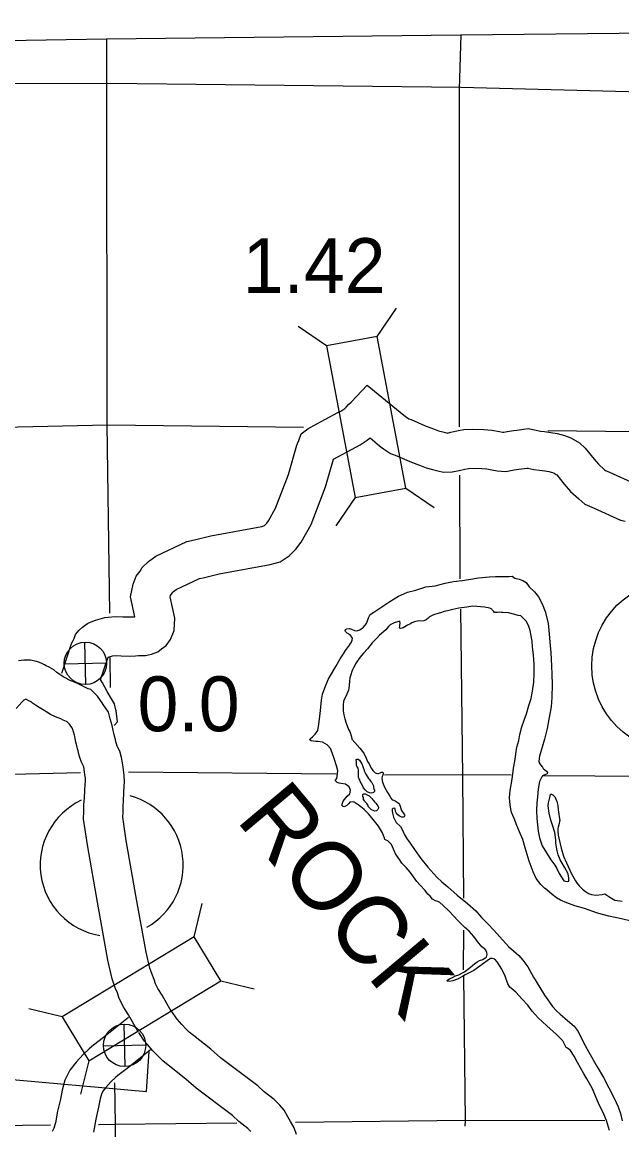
# Model space of a CAD drawing. Extents: x 77230 to 630905, y 790554 to 1662844.
# Drawn here: x 342524 to 351748, y 1622566 to 1639610 of the extents above; entities that cross this region are included whole.
import ezdxf

# ---------------------------------------------------------------- set-up
doc = ezdxf.new("R2010")
doc.units = 0
for name, color, linetype in [('Level 14', 7, 'Continuous'), ('Level 16', 7, 'Continuous'), ('Level 17', 7, 'Continuous'), ('Level 19', 7, 'Continuous'), ('Level 22', 7, 'Continuous'), ('Level 23', 7, 'Continuous'), ('Level 26', 7, 'Continuous'), ('Level 31', 7, 'Continuous'), ('Level 32', 7, 'Continuous'), ('Level 33', 7, 'Continuous'), ('Level 34', 7, 'Continuous')]:
    doc.layers.add(name, color=color, linetype=linetype)

msp = doc.modelspace()

# ---------------------------------------------------------------- linework, layer by layer
at = {"layer": 'Level 14'}
msp.add_lwpolyline([(338556, 1639267), (343823, 1639351), (349273, 1639417), (354630, 1639473), (359059, 1639529), (364378, 1639584), (367437, 1639610)], dxfattribs=at)
at = {"layer": 'Level 16'}
for points in [[(343823, 1639351), (343819, 1638672), (343825, 1633418), (343865, 1630514)], [(349273, 1639417), (349244, 1638581), (349246, 1633383)], [(354631, 1638464), (349271, 1638604), (343841, 1638666), (338567, 1638659), (333182, 1638541)], [(346851, 1633371), (343835, 1633410), (338542, 1633291), (336598, 1633267)], [(354599, 1633274), (350612, 1633323)], [(349249, 1632641), (349255, 1631046)], [(349264, 1630580), (349295, 1628000), (349311, 1626130)], [(343874, 1629832), (343880, 1629370)], [(343419, 1628061), (338580, 1627939), (333319, 1627911)], [(347353, 1628041), (344162, 1628071)], [(350045, 1628023), (349285, 1628028), (348095, 1628025)], [(354575, 1627989), (350525, 1628014)], [(349312, 1625639), (349308, 1625030)], [(349315, 1624934), (349336, 1622709), (349335, 1622623)], [(343946, 1623291), (343953, 1622646), (343954, 1621548)], [(342958, 1622636), (338648, 1622586), (333384, 1622611)], [(345827, 1622668), (343947, 1622648), (343700, 1622645)], [(351487, 1622703), (349340, 1622707), (346730, 1622678)]]:
    msp.add_lwpolyline(points, dxfattribs=at)
at = {"layer": 'Level 17'}
for points in [[(347460, 1627539), (347440, 1627559), (347464, 1627623), (347523, 1627700), (347566, 1627738), (347574, 1627794), (347553, 1627842), (347497, 1627883), (347433, 1627893), (347399, 1627899), (347367, 1627912), (347339, 1627942), (347364, 1627974), (347381, 1628089), (347360, 1628168), (347323, 1628282), (347292, 1628368), (347266, 1628434), (347215, 1628491), (347145, 1628533), (347077, 1628540), (347043, 1628542), (347003, 1628545), (346969, 1628553), (346948, 1628569), (346952, 1628583), (346990, 1628611), (347030, 1628652), (347073, 1628710), (347086, 1628807), (347109, 1628967), (347129, 1629177), (347146, 1629272), (347181, 1629368), (347233, 1629497), (347267, 1629559), (347350, 1629694), (347416, 1629813), (347466, 1629890), (347495, 1629940), (347529, 1629984), (347558, 1630025), (347574, 1630047), (347590, 1630071), (347602, 1630101), (347603, 1630133), (347567, 1630183), (347525, 1630207), (347496, 1630236), (347490, 1630250), (347498, 1630262), (347518, 1630273), (347558, 1630279), (347590, 1630269), (347638, 1630250), (347672, 1630246), (347720, 1630259), (347776, 1630303), (347821, 1630356), (347833, 1630380), (347850, 1630444), (347878, 1630495), (347931, 1630533), (348088, 1630633), (348178, 1630696), (348315, 1630777), (348452, 1630839), (348580, 1630868), (348734, 1630920), (348879, 1630937), (349029, 1630979), (349161, 1631002), (349294, 1631021), (349396, 1631036), (349542, 1631058), (349706, 1631073), (349806, 1631078), (349928, 1631078), (350012, 1631080), (350060, 1631083), (350104, 1631057), (350170, 1631040), (350224, 1631018), (350279, 1630989), (350323, 1630919), (350404, 1630846), (350465, 1630767), (350524, 1630659), (350567, 1630543), (350617, 1630364), (350630, 1630193), (350641, 1630075), (350655, 1629903), (350667, 1629703), (350670, 1629571), (350676, 1629425), (350672, 1629219), (350661, 1629074), (350627, 1628886), (350602, 1628741), (350560, 1628579)], [(350393, 1629456), (350400, 1629590), (350399, 1629725), (350387, 1629873), (350374, 1629991), (350367, 1630085), (350338, 1630251), (350311, 1630328), (350276, 1630392), (350194, 1630477), (350154, 1630481), (350103, 1630495), (350005, 1630522), (349917, 1630525), (349893, 1630527), (349859, 1630530), (349837, 1630524), (349791, 1630528), (349777, 1630541), (349755, 1630565), (349749, 1630575), (349717, 1630591), (349638, 1630610), (349458, 1630622), (349362, 1630609), (349323, 1630603), (349243, 1630592), (349151, 1630573), (349069, 1630552), (349015, 1630540), (348957, 1630521), (348900, 1630505), (348868, 1630494), (348832, 1630482), (348800, 1630464), (348792, 1630460), (348776, 1630445), (348766, 1630433), (348736, 1630413), (348701, 1630399), (348645, 1630394), (348623, 1630398), (348561, 1630381), (348517, 1630365), (348487, 1630348), (348453, 1630330), (348410, 1630306), (348384, 1630291), (348368, 1630285), (348346, 1630279), (348334, 1630281), (348328, 1630297), (348331, 1630315), (348333, 1630329), (348339, 1630355), (348331, 1630393), (348247, 1630366), (348187, 1630335), (348161, 1630311), (348116, 1630261), (348023, 1630176), (347979, 1630129), (347908, 1630060), (347835, 1629969), (347774, 1629899), (347718, 1629836), (347661, 1629751), (347618, 1629677), (347602, 1629635), (347575, 1629552), (347565, 1629520), (347560, 1629470), (347554, 1629404), (347551, 1629364), (347545, 1629332), (347529, 1629296), (347506, 1629245), (347476, 1629185), (347467, 1629155), (347461, 1629103), (347460, 1629047), (347464, 1629011), (347473, 1628951), (347485, 1628889), (347510, 1628825), (347543, 1628727), (347563, 1628693), (347590, 1628613), (347596, 1628579), (347643, 1628528), (347720, 1628438), (347760, 1628389), (347783, 1628349), (347817, 1628287), (347836, 1628235), (347860, 1628195), (347876, 1628160), (347895, 1628128), (347917, 1628096), (347955, 1628058), (347969, 1628052)], [(351893, 1625777), (351741, 1625813), (351548, 1625853), (351376, 1625902), (351173, 1625970), (351023, 1626012), (350900, 1626061), (350806, 1626102), (350744, 1626138), (350675, 1626185), (350592, 1626258), (350560, 1626286), (350500, 1626339), (350431, 1626431), (350382, 1626538), (350324, 1626700), (350262, 1626906), (350223, 1627034), (350176, 1627153), (350133, 1627251), (350090, 1627355), (350053, 1627450), (350042, 1627498), (350030, 1627566), (350021, 1627674), (350030, 1627787), (350054, 1627929), (350069, 1628039), (350084, 1628129), (350105, 1628262), (350116, 1628350), (350135, 1628452), (350164, 1628559), (350179, 1628647), (350210, 1628768), (350245, 1628868), (350280, 1628966), (350319, 1629095), (350352, 1629203), (350375, 1629314), (350393, 1629456)], [(350560, 1628579), (350506, 1628402), (350481, 1628314), (350473, 1628239), (350478, 1628211), (350498, 1628184), (350526, 1628144), (350540, 1628126), (350563, 1628104), (350589, 1628084), (350603, 1628063), (350597, 1628042), (350537, 1628020), (350516, 1627998), (350482, 1627927), (350463, 1627809), (350449, 1627691), (350443, 1627598), (350437, 1627478), (350440, 1627356), (350462, 1627164), (350483, 1627058), (350524, 1626936), (350591, 1626827), (350658, 1626721), (350717, 1626638), (350749, 1626586), (350786, 1626510), (350819, 1626453), (350855, 1626397), (350883, 1626393), (350909, 1626386), (350931, 1626392), (350935, 1626440), (350920, 1626506), (350865, 1626609), (350828, 1626671), (350802, 1626721), (350769, 1626799), (350755, 1626859), (350744, 1626913), (350733, 1626977), (350731, 1627021), (350729, 1627071), (350716, 1627141), (350683, 1627252), (350656, 1627332), (350629, 1627440), (350614, 1627550), (350621, 1627598), (350639, 1627682), (350650, 1627727), (350652, 1627729), (350668, 1627733), (350688, 1627721), (350717, 1627689), (350735, 1627653), (350747, 1627619), (350762, 1627558), (350770, 1627492), (350781, 1627424), (350786, 1627380), (350792, 1627328), (350790, 1627309), (350783, 1627277), (350767, 1627221), (350763, 1627203), (350762, 1627157), (350768, 1627099), (350779, 1627053), (350798, 1626965), (350814, 1626899), (350851, 1626775), (350896, 1626674), (350976, 1626506), (351033, 1626399), (351051, 1626369), (351094, 1626321), (351144, 1626270), (351187, 1626232), (351233, 1626201), (351279, 1626187), (351349, 1626176), (351443, 1626189), (351487, 1626197), (351561, 1626148), (351638, 1626100), (351754, 1626086)], [(347766, 1627856), (347725, 1627924), (347716, 1627950), (347706, 1627967), (347700, 1627987), (347698, 1627997), (347698, 1628015), (347699, 1628033), (347699, 1628053), (347699, 1628069), (347695, 1628091), (347696, 1628099), (347692, 1628129), (347674, 1628163), (347669, 1628179), (347667, 1628205), (347665, 1628217), (347665, 1628239), (347664, 1628247), (347662, 1628257), (347664, 1628263), (347678, 1628267), (347690, 1628268), (347712, 1628254), (347727, 1628230), (347747, 1628198), (347766, 1628159), (347774, 1628127), (347778, 1628117), (347791, 1628077), (347809, 1628037)], [(347809, 1628037), (347850, 1627973), (347866, 1627956), (347885, 1627926), (347901, 1627908), (347926, 1627860), (347930, 1627834), (347934, 1627808), (347943, 1627793), (347941, 1627772), (347929, 1627758), (347919, 1627752), (347891, 1627748), (347867, 1627749), (347829, 1627765), (347801, 1627797), (347776, 1627828), (347766, 1627856)], [(347969, 1628052), (347991, 1628051), (348005, 1628051), (348031, 1628059), (348053, 1628067), (348065, 1628071), (348081, 1628052), (348079, 1628045), (348077, 1628039), (348072, 1628023), (348064, 1628001), (348056, 1627971), (348065, 1627917), (348095, 1627841), (348146, 1627758), (348181, 1627698), (348201, 1627664), (348213, 1627646), (348219, 1627644), (348239, 1627639), (348263, 1627629), (348292, 1627609), (348314, 1627593), (348328, 1627573), (348340, 1627545), (348349, 1627511), (348359, 1627480), (348369, 1627464), (348383, 1627444), (348395, 1627430), (348407, 1627414), (348408, 1627402), (348400, 1627382), (348382, 1627378), (348364, 1627379), (348338, 1627387), (348324, 1627397), (348301, 1627415), (348279, 1627445), (348269, 1627465), (348261, 1627507), (348255, 1627517), (348225, 1627508), (348215, 1627498), (348215, 1627476), (348219, 1627436), (348234, 1627376), (348277, 1627295), (348343, 1627233), (348382, 1627157), (348398, 1627113), (348447, 1627038), (348484, 1626990), (348567, 1626865), (348654, 1626740), (348765, 1626607), (348901, 1626452), (348979, 1626382), (349070, 1626305), (349213, 1626178), (349375, 1626046), (349500, 1625935), (349591, 1625834), (349698, 1625725), (349776, 1625645), (349874, 1625534), (350007, 1625385), (350082, 1625318), (350122, 1625284), (350164, 1625249), (350223, 1625179), (350302, 1625072), (350387, 1624917), (350485, 1624755), (350560, 1624640), (350611, 1624566), (350682, 1624465), (350742, 1624397), (350801, 1624346), (350873, 1624285), (350946, 1624219), (351013, 1624162), (351075, 1624080), (351159, 1623911), (351238, 1623762), (351371, 1623537), (351464, 1623369), (351550, 1623210), (351631, 1623051), (351693, 1622921), (351726, 1622819), (351753, 1622703)], [(351294, 1623207), (351208, 1623353), (351156, 1623440), (351068, 1623602), (351015, 1623699), (350956, 1623789), (350914, 1623820), (350890, 1623832), (350874, 1623862), (350841, 1623936), (350742, 1624035), (350595, 1624164), (350463, 1624288), (350368, 1624392), (350300, 1624485), (350215, 1624574), (350116, 1624682), (350027, 1624761), (349992, 1624812), (349951, 1624928), (349904, 1625040), (349829, 1625153), (349793, 1625191), (349755, 1625201), (349727, 1625200), (349679, 1625168), (349621, 1625127), (349562, 1625083), (349469, 1625016), (349401, 1624983), (349337, 1624950), (349299, 1624926), (349220, 1624885), (349150, 1624856), (349092, 1624846), (349064, 1624851), (349056, 1624863), (349098, 1624888), (349142, 1624908), (349187, 1624933), (349241, 1624953), (349285, 1624974), (349327, 1624998), (349374, 1625033), (349418, 1625067), (349454, 1625099), (349482, 1625122), (349525, 1625150), (349561, 1625169), (349609, 1625185), (349647, 1625210), (349665, 1625224), (349676, 1625264), (349674, 1625292), (349658, 1625330), (349637, 1625354), (349617, 1625365), (349597, 1625383), (349579, 1625401), (349542, 1625443), (349473, 1625540), (349399, 1625622), (349334, 1625677), (349231, 1625782), (349090, 1625933), (348999, 1626018), (348951, 1626062), (348916, 1626081), (348884, 1626089), (348838, 1626115), (348800, 1626160), (348765, 1626192), (348721, 1626246), (348648, 1626333), (348597, 1626389), (348492, 1626528), (348431, 1626601), (348389, 1626641), (348363, 1626671), (348330, 1626728), (348269, 1626812), (348235, 1626882), (348204, 1626957), (348149, 1627015), (348121, 1627023), (348105, 1627032), (348097, 1627054), (348068, 1627134), (348003, 1627236), (347900, 1627369), (347851, 1627426), (347785, 1627496), (347734, 1627537), (347692, 1627567), (347630, 1627608), (347602, 1627614), (347564, 1627608), (347548, 1627588), (347516, 1627557), (347478, 1627535), (347460, 1627539)], [(347773, 1627648), (347772, 1627680), (347766, 1627694), (347766, 1627722), (347766, 1627724), (347771, 1627732), (347779, 1627734), (347799, 1627734), (347822, 1627725), (347864, 1627703), (347900, 1627662), (347919, 1627642), (347935, 1627626), (347945, 1627614), (347965, 1627593), (347994, 1627553)], [(347994, 1627553), (348006, 1627527), (348004, 1627513), (347993, 1627493), (347985, 1627483), (347973, 1627476), (347949, 1627470), (347899, 1627491), (347887, 1627501), (347848, 1627543), (347844, 1627555), (347827, 1627585), (347801, 1627612), (347797, 1627622), (347773, 1627648)], [(351558, 1622555), (351511, 1622709), (351470, 1622809), (351390, 1622978), (351294, 1623207)]]:
    msp.add_lwpolyline(points, dxfattribs=at)
at = {"layer": 'Level 19'}
for p, q in [((347983, 1634775), (348281, 1635211)), ((347205, 1634629), (346769, 1634927)), ((348423, 1632440), (348859, 1632143)), ((347645, 1632294), (347347, 1631858)), ((345169, 1625536), (345294, 1626049)), ((345580, 1624859), (346093, 1624734)), ((343138, 1624304), (342625, 1624429)), ((343549, 1623627), (343423, 1623114))]:
    msp.add_line(p, q, dxfattribs=at)
for points in [[(348423, 1632440), (347983, 1634775), (347205, 1634629), (347645, 1632294)], [(345169, 1625536), (343138, 1624304), (343549, 1623627), (345580, 1624859)]]:
    msp.add_lwpolyline(points, close=True, dxfattribs=at)
at = {"layer": 'Level 22'}
for points in [[(343132, 1629593), (343284, 1630048), (343306, 1630094), (343322, 1630127), (343346, 1630190), (343399, 1630255), (343450, 1630303), (343491, 1630333), (343530, 1630358), (343586, 1630384), (343654, 1630407), (343797, 1630447), (343954, 1630466), (344074, 1630460), (344178, 1630457), (344225, 1630459), (344255, 1630461), (344188, 1630766), (344209, 1630865), (344229, 1630961), (344277, 1631087), (344338, 1631164), (344372, 1631221), (344468, 1631309), (344579, 1631393), (345056, 1631620), (345176, 1631646), (345427, 1631706), (346210, 1631851), (346239, 1631859), (346250, 1631866), (346287, 1631902), (346313, 1631936), (346422, 1632134), (346619, 1632651), (346751, 1633099), (346756, 1633113), (346761, 1633129), (346778, 1633174), (346816, 1633274), (346920, 1633354), (346966, 1633378), (346999, 1633397), (347381, 1633606), (347424, 1633626), (347485, 1633667), (347498, 1633677), (347505, 1633683), (347510, 1633687), (347544, 1633728), (347586, 1633764), (347832, 1634026), (348394, 1633565), (348438, 1633531), (348471, 1633508), (348509, 1633494), (348713, 1633406), (348852, 1633354), (348927, 1633324), (348993, 1633306), (349055, 1633289), (349061, 1633288), (349069, 1633288), (349116, 1633299), (349208, 1633319), (349316, 1633341), (349456, 1633348), (349627, 1633342), (349750, 1633334), (349867, 1633311), (349912, 1633302), (349933, 1633301), (349986, 1633310), (350080, 1633327), (350132, 1633332), (350306, 1633359), (350430, 1633332)], [(343937, 1628786), (343992, 1628842), (343968, 1629011), (343960, 1629051), (343942, 1629119), (343899, 1629199), (343829, 1629313), (343758, 1629442), (343734, 1629487), (343732, 1629491), (343731, 1629494), (343841, 1629822), (343847, 1629833), (343849, 1629839), (343915, 1629857), (343977, 1629864), (344049, 1629861), (344181, 1629856), (344266, 1629860), (344313, 1629864), (344352, 1629865), (344420, 1629866), (344514, 1629883), (344609, 1629923), (344668, 1629965), (344741, 1630019), (344808, 1630110), (344864, 1630248), (344873, 1630440), (344802, 1630769), (344805, 1630788), (344833, 1630823), (344843, 1630839), (344853, 1630848), (344893, 1630878), (345250, 1631048), (345309, 1631061), (345552, 1631119), (346341, 1631265), (346491, 1631304), (346631, 1631400), (346736, 1631502), (346816, 1631606), (346968, 1631880), (347188, 1632459), (347313, 1632885), (347656, 1633072), (347724, 1633105), (347833, 1633178), (347864, 1633202), (347878, 1633212), (348023, 1633092), (348084, 1633047), (348188, 1632973), (348287, 1632936), (348489, 1632850), (348636, 1632794), (348737, 1632754), (348836, 1632727), (348919, 1632705), (349005, 1632687), (349140, 1632689), (349245, 1632713), (349332, 1632732), (349392, 1632744), (349460, 1632748), (349596, 1632743), (349673, 1632737), (349749, 1632723), (349832, 1632706), (349964, 1632697), (350090, 1632719), (350163, 1632732), (350207, 1632736), (350289, 1632749), (350305, 1632746)], [(350431, 1633332), (350495, 1633318), (350560, 1633311), (350658, 1633297), (350752, 1633281), (350865, 1633251), (350965, 1633214), (351097, 1633137), (351186, 1633054), (351322, 1632886), (351388, 1632809), (351484, 1632721), (351496, 1632711), (351560, 1632685), (351942, 1632512)], [(350304, 1632746), (350396, 1632726), (350483, 1632716), (350566, 1632704), (350625, 1632694), (350684, 1632678), (350708, 1632669), (350737, 1632652), (350746, 1632644), (350862, 1632500), (350958, 1632390), (351085, 1632273), (351179, 1632193), (351323, 1632134), (351730, 1631949), (351798, 1631929)], [(344161, 1624296), (343774, 1623985), (343620, 1623871), (343553, 1623812), (343460, 1623723), (343356, 1623609), (343255, 1623483), (343179, 1623328), (343138, 1623176), (343113, 1623040), (343069, 1622852), (343038, 1622676), (343011, 1622592), (342987, 1622539)], [(344500, 1623798), (344141, 1623510), (343998, 1623404), (343958, 1623369), (343890, 1623304), (343812, 1623219), (343764, 1623159), (343743, 1623115), (343723, 1623043), (343700, 1622917), (343657, 1622732), (343621, 1622530)]]:
    msp.add_lwpolyline(points, dxfattribs=at)
at = {"layer": 'Level 23'}
for points in [[(343851, 1628992), (343771, 1629110), (343753, 1629136), (343730, 1629173), (343682, 1629237), (343582, 1629341), (343537, 1629353), (343467, 1629387), (343427, 1629406), (343374, 1629434), (343277, 1629474), (343237, 1629492), (343204, 1629511), (343167, 1629533), (343106, 1629569), (343071, 1629592), (343056, 1629603), (343013, 1629645), (342937, 1629683), (342895, 1629706), (342865, 1629720), (342838, 1629735), (342782, 1629763), (342726, 1629776), (342650, 1629794), (342551, 1629792), (342467, 1629783)], [(343298, 1628739), (343251, 1628806), (343251, 1628807), (343214, 1628843), (343205, 1628847), (343156, 1628870), (343121, 1628889), (343037, 1628923), (342960, 1628959), (342904, 1628991), (342861, 1629016), (342785, 1629062), (342731, 1629098), (342670, 1629142), (342660, 1629151), (342629, 1629168), (342590, 1629186), (342580, 1629191), (342570, 1629188), (342570, 1629188), (342550, 1629176), (342526, 1629152), (342432, 1629051)], [(344823, 1624383), (344676, 1624638), (344612, 1624743), (344575, 1624813), (344555, 1624879), (344516, 1624970), (344487, 1625054), (344429, 1625299), (344274, 1626174), (344125, 1627019), (344071, 1627378), (344075, 1627450), (344075, 1627547), (344081, 1627630), (344088, 1627750), (344095, 1627860), (344096, 1627917), (344095, 1628022), (344084, 1628106), (344069, 1628213), (344054, 1628296), (344024, 1628392), (343989, 1628460), (343986, 1628469), (343977, 1628505), (343967, 1628538), (343960, 1628573), (343945, 1628623), (343935, 1628668), (343924, 1628712), (343920, 1628736), (343908, 1628787), (343880, 1628889), (343873, 1628913), (343851, 1628992)], [(344303, 1624083), (344159, 1624333), (344088, 1624450), (344017, 1624587), (343991, 1624672), (343956, 1624753), (343910, 1624888), (343841, 1625178), (343684, 1626069), (343533, 1626922), (343469, 1627347), (343475, 1627467), (343475, 1627571), (343483, 1627668), (343489, 1627785), (343495, 1627887), (343496, 1627922), (343496, 1627978), (343489, 1628026), (343477, 1628118), (343470, 1628151), (343467, 1628163), (343436, 1628222), (343410, 1628297), (343398, 1628345), (343383, 1628395), (343377, 1628429), (343363, 1628474), (343351, 1628533), (343337, 1628588), (343332, 1628617), (343327, 1628637), (343298, 1628739)], [(346746, 1622495), (346709, 1622596), (346653, 1622692), (346611, 1622768), (346552, 1622868), (346485, 1622943), (346402, 1623033), (346246, 1623151), (346151, 1623243), (345577, 1623674), (345428, 1623806), (345158, 1624019), (345093, 1624069), (345047, 1624116), (344980, 1624184), (344909, 1624269), (344881, 1624302), (344809, 1624405)], [(346041, 1622539), (345997, 1622587), (345855, 1622694), (345759, 1622787), (345198, 1623209), (345043, 1623345), (344788, 1623546), (344691, 1623622), (344619, 1623696), (344536, 1623779), (344453, 1623880), (344408, 1623931), (344317, 1624061)]]:
    msp.add_lwpolyline(points, dxfattribs=at)
at = {"layer": 'Level 26'}
for start, end in [(115.1448, 260.5377), (299.3578, 74.9316)]:
    msp.add_arc((343901, 1626641), 1100, start, end, dxfattribs=at)
at = {"layer": 'Level 31'}
for p, q in [((338399, 1623692), (344437, 1623154)), ((344437, 1623154), (344477, 1623776))]:
    msp.add_line(p, q, dxfattribs=at)
at = {"layer": 'Level 33'}
msp.add_circle((352607, 1629704), 1320, dxfattribs=at)
at = {"layer": 'Level 34'}
for p, q in [((343505, 1629418), (343490, 1630069)), ((343172, 1629736), (343823, 1629751)), ((344107, 1623539), (344092, 1624190)), ((343774, 1623857), (344425, 1623872))]:
    msp.add_line(p, q, dxfattribs=at)
for centre in [(343497, 1629744), (344099, 1623865)]:
    msp.add_circle(centre, 326, dxfattribs=at)

# ---------------------------------------------------------------- texts
at = {"layer": 'Level 17'}
msp.add_text('ROCK', height=1056, rotation=310, dxfattribs=at).set_placement((345799, 1627335))
at = {"layer": 'Level 31'}
msp.add_text('0.0', height=844.8, dxfattribs=at).set_placement((344299, 1628699))
at = {"layer": 'Level 32'}
msp.add_text('1.42', height=844.8, dxfattribs=at).set_placement((345915, 1635441))

doc.saveas('drawing.dxf')
